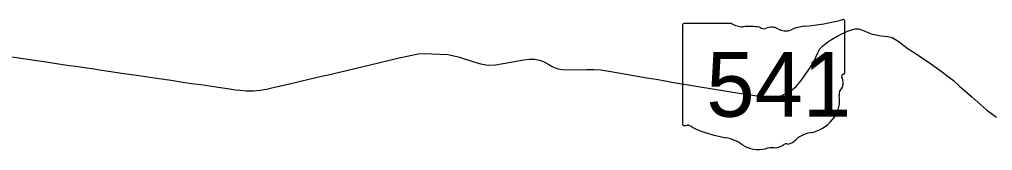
# Model space of a CAD drawing. Extents: x 2004415 to 2276415, y 751181 to 927181.
# Drawn here: x 2107694 to 2124487, y 819345 to 821612 of the extents above; entities that cross this region are included whole.
import ezdxf

# ---------------------------------------------------------------- set-up
doc = ezdxf.new("R2010")
doc.units = 0
doc.layers.add('GM_X_State_Route', color=7, linetype='Continuous')
doc.layers.add('GM_X_State_Shield', color=7, linetype='Continuous')

msp = doc.modelspace()

# ---------------------------------------------------------------- linework, layer by layer
at = {"layer": 'GM_X_State_Route'}
msp.add_line((2113000, 820651), (2113359, 820736), dxfattribs=at)
for points in [[(2113359, 820736), (2113602, 820795), (2113891, 820862), (2114080, 820910), (2114194, 820934), (2114572, 821015), (2114680, 821024), (2114943, 821014), (2115089, 821005), (2115170, 820990), (2115286, 820960), (2115554, 820875), (2115656, 820847), (2115745, 820828), (2115814, 820822), (2115908, 820828), (2116043, 820852), (2116401, 820916), (2116494, 820925), (2116581, 820923), (2116666, 820910), (2116737, 820887), (2116828, 820834), (2116899, 820790), (2116987, 820759), (2117072, 820747), (2117204, 820740), (2117482, 820745), (2117608, 820749), (2117728, 820738), (2117868, 820720), (2118166, 820666), (2118555, 820598), (2118681, 820578), (2118806, 820554), (2118954, 820530), (2119408, 820455), (2120150, 820334), (2120349, 820301), (2120518, 820273), (2120597, 820262), (2120664, 820258), (2120719, 820262), (2120760, 820272), (2120840, 820294), (2120944, 820345), (2121034, 820401), (2121096, 820455), (2121185, 820559), (2121237, 820630), (2121344, 820787), (2121402, 820886), (2121471, 821034), (2121509, 821105), (2121557, 821154), (2121618, 821203), (2121656, 821230), (2121710, 821267), (2121806, 821324), (2121986, 821410), (2122055, 821434), (2122117, 821449), (2122181, 821447), (2122243, 821427), (2122350, 821381), (2122412, 821359), (2122478, 821344), (2122565, 821331), (2122679, 821316), (2122753, 821297), (2122812, 821267), (2122877, 821227), (2122955, 821164), (2123032, 821103), (2123105, 821056), (2123256, 820959), (2123397, 820859), (2123601, 820717), (2123723, 820628), (2123811, 820556), (2123918, 820461), (2124127, 820276), (2124285, 820134), (2124388, 820046), (2124469, 819985), (2124554, 819924)], [(2107212, 821015), (2107915, 820914), (2108154, 820878), (2108480, 820829), (2108560, 820816), (2108669, 820802), (2108859, 820773), (2108941, 820761), (2109109, 820736), (2109269, 820713), (2109457, 820685), (2109756, 820643), (2109909, 820619), (2110062, 820597), (2110312, 820560), (2110513, 820530), (2110664, 820507), (2110824, 820485), (2111046, 820452), (2111319, 820410), (2111424, 820395), (2111496, 820387), (2111609, 820379), (2111733, 820379), (2111840, 820390), (2111955, 820408), (2112098, 820441), (2112331, 820495), (2112712, 820583), (2112959, 820642), (2113000, 820651)]]:
    msp.add_lwpolyline(points, dxfattribs=at)
at = {"layer": 'GM_X_State_Shield'}
for p, q in [((2119134, 821511), (2119134, 819810)), ((2119982, 821541), (2119162, 821541)), ((2121936, 820693), (2121936, 821583)), ((2121936, 820693), (2121936, 820693))]:
    msp.add_line(p, q, dxfattribs=at)
for centre, major_axis, start_param, end_param in [((2119166, 821515), (32.5, 0), 1.712693, 3.28349), ((2120178, 821738), (315, 0), 4.042523, 4.731795), ((2120938, 823860), (2971, 0), 4.814394, 5.042369), ((2121905, 821586), (31.2, 0), 6.141152, 7.989035), ((2120282, 820586), (1130, 0), 1.404758, 1.657858), ((2120539, 821524), (90.8, 0), 3.836095, 5.185415), ((2120672, 821327), (189, 0), 0.950623, 2.079405), ((2120916, 821597), (227, 0), 4.081561, 5.145723), ((2121317, 821021), (598, 0), 1.699011, 2.107814), ((2121903, 820689), (33.4, 0), 5.05454, 6.418171), ((2121929, 820628), (48.3, 0), 1.883978, 3.671073), ((2121622, 820515), (290, 0), 5.934695, 6.695948), ((2122048, 820320), (211, 0), 2.387724, 3.262537), ((2121105, 820207), (743, 0), 5.101752, 6.440018), ((2119167, 819806), (32.7, 0), 3.00124, 4.508301), ((2119172, 819980), (250, 0), 4.665946, 4.897461), ((2119223, 819712), (90.1, 0), 0.519207, 1.627899), ((2120361, 821240), (2146, 0), 4.195997, 4.488961), ((2121418, 819333), (407, 0), 1.647645, 2.488434), ((2119721, 819046), (671, 0), 0.823519, 1.323587), ((2120902, 819645), (240, 0), 4.937069, 5.64225), ((2120447, 819704), (426, 0), 4.026481, 4.996735), ((2120693, 819115), (350, 0), 1.495662, 1.94098), ((2120724, 819576), (227, 0), 4.691044, 5.507374), ((2120929, 819411), (63.9, 0), 1.147584, 2.315152)]:
    msp.add_ellipse(centre, major_axis=major_axis, ratio=0.8, start_param=start_param, end_param=end_param, dxfattribs=at)

# ---------------------------------------------------------------- texts
msp.add_text('541', height=1120.7, dxfattribs=at).set_placement((2119547, 819930))

doc.saveas('drawing.dxf')
